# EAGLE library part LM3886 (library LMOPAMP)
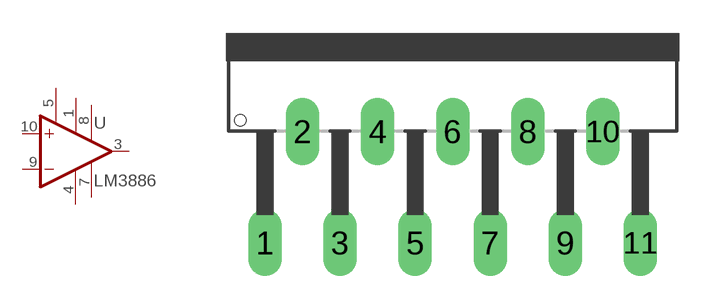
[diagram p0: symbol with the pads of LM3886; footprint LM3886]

Designator prefix -

## LM3886  [LM3886]
1  V+  pwr
3  OUT  out
4  V-  pwr
5  5
7  7
8  8
9  -IN  in
10  +IN  in

## Footprint LM3886 (pad centres in mm)
drill 1.016 long: 1 -22.479,3.175; 2 -20.777,8.23; 3 -19.075,3.175; 4 -17.374,8.23; 5 -15.672,3.175; 6 -13.97,8.23; 7 -12.268,3.175; 8 -10.566,8.23; 9 -8.865,3.175; 10 -7.163,8.23; 11 -5.461,3.175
